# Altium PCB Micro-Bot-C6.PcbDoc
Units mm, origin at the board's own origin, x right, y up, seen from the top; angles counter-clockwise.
Board outline 64.69 x 63 mm, 2 copper layers (Top Layer, Bottom Layer); 16 components, 18 nets, 55 pads, 0 vias.
Unrouted connection lines stored in the file: 2.
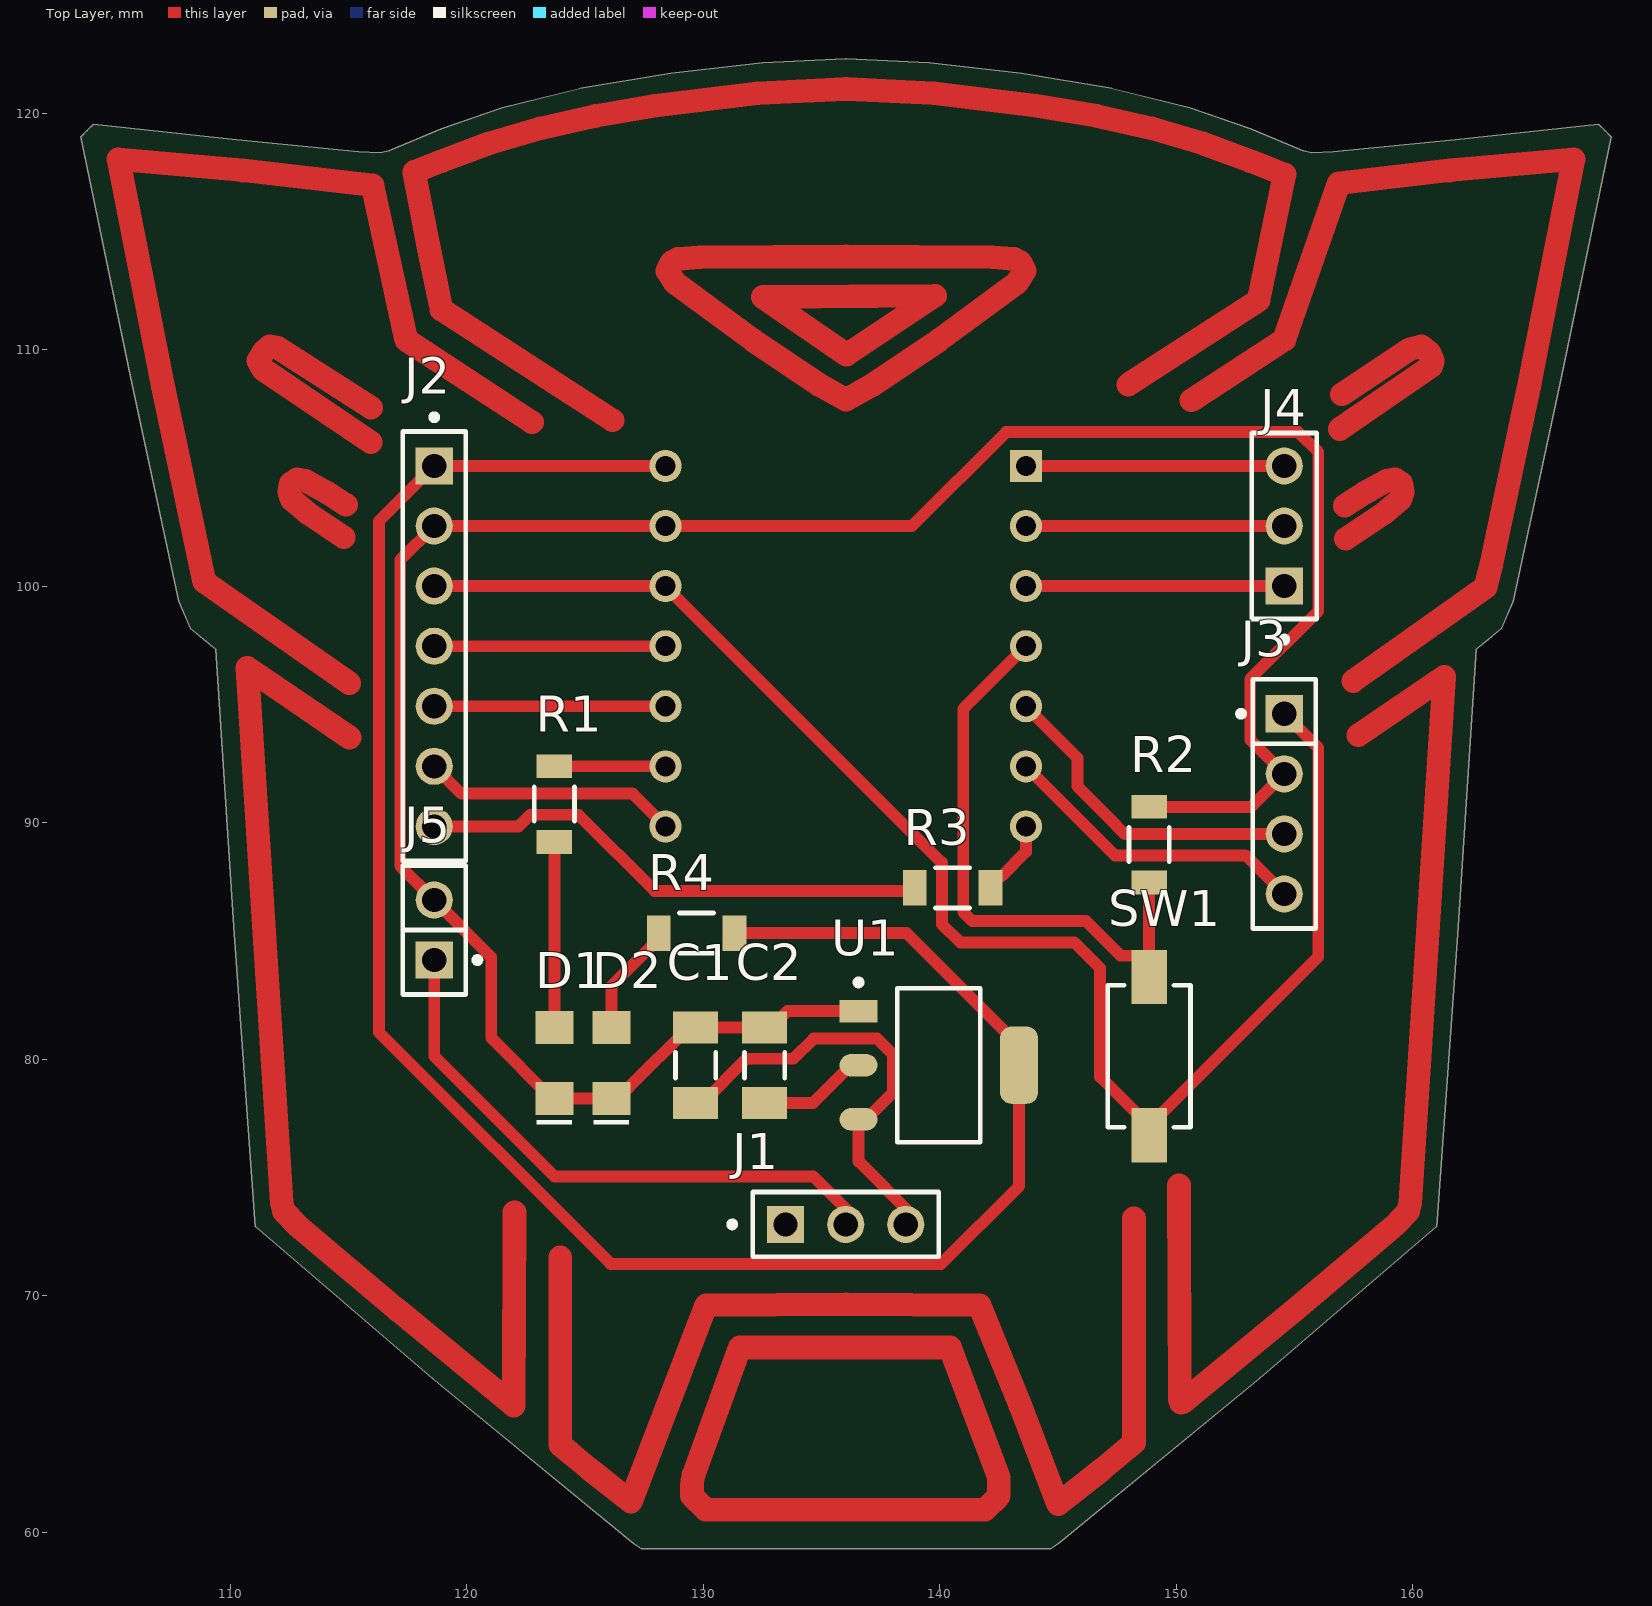
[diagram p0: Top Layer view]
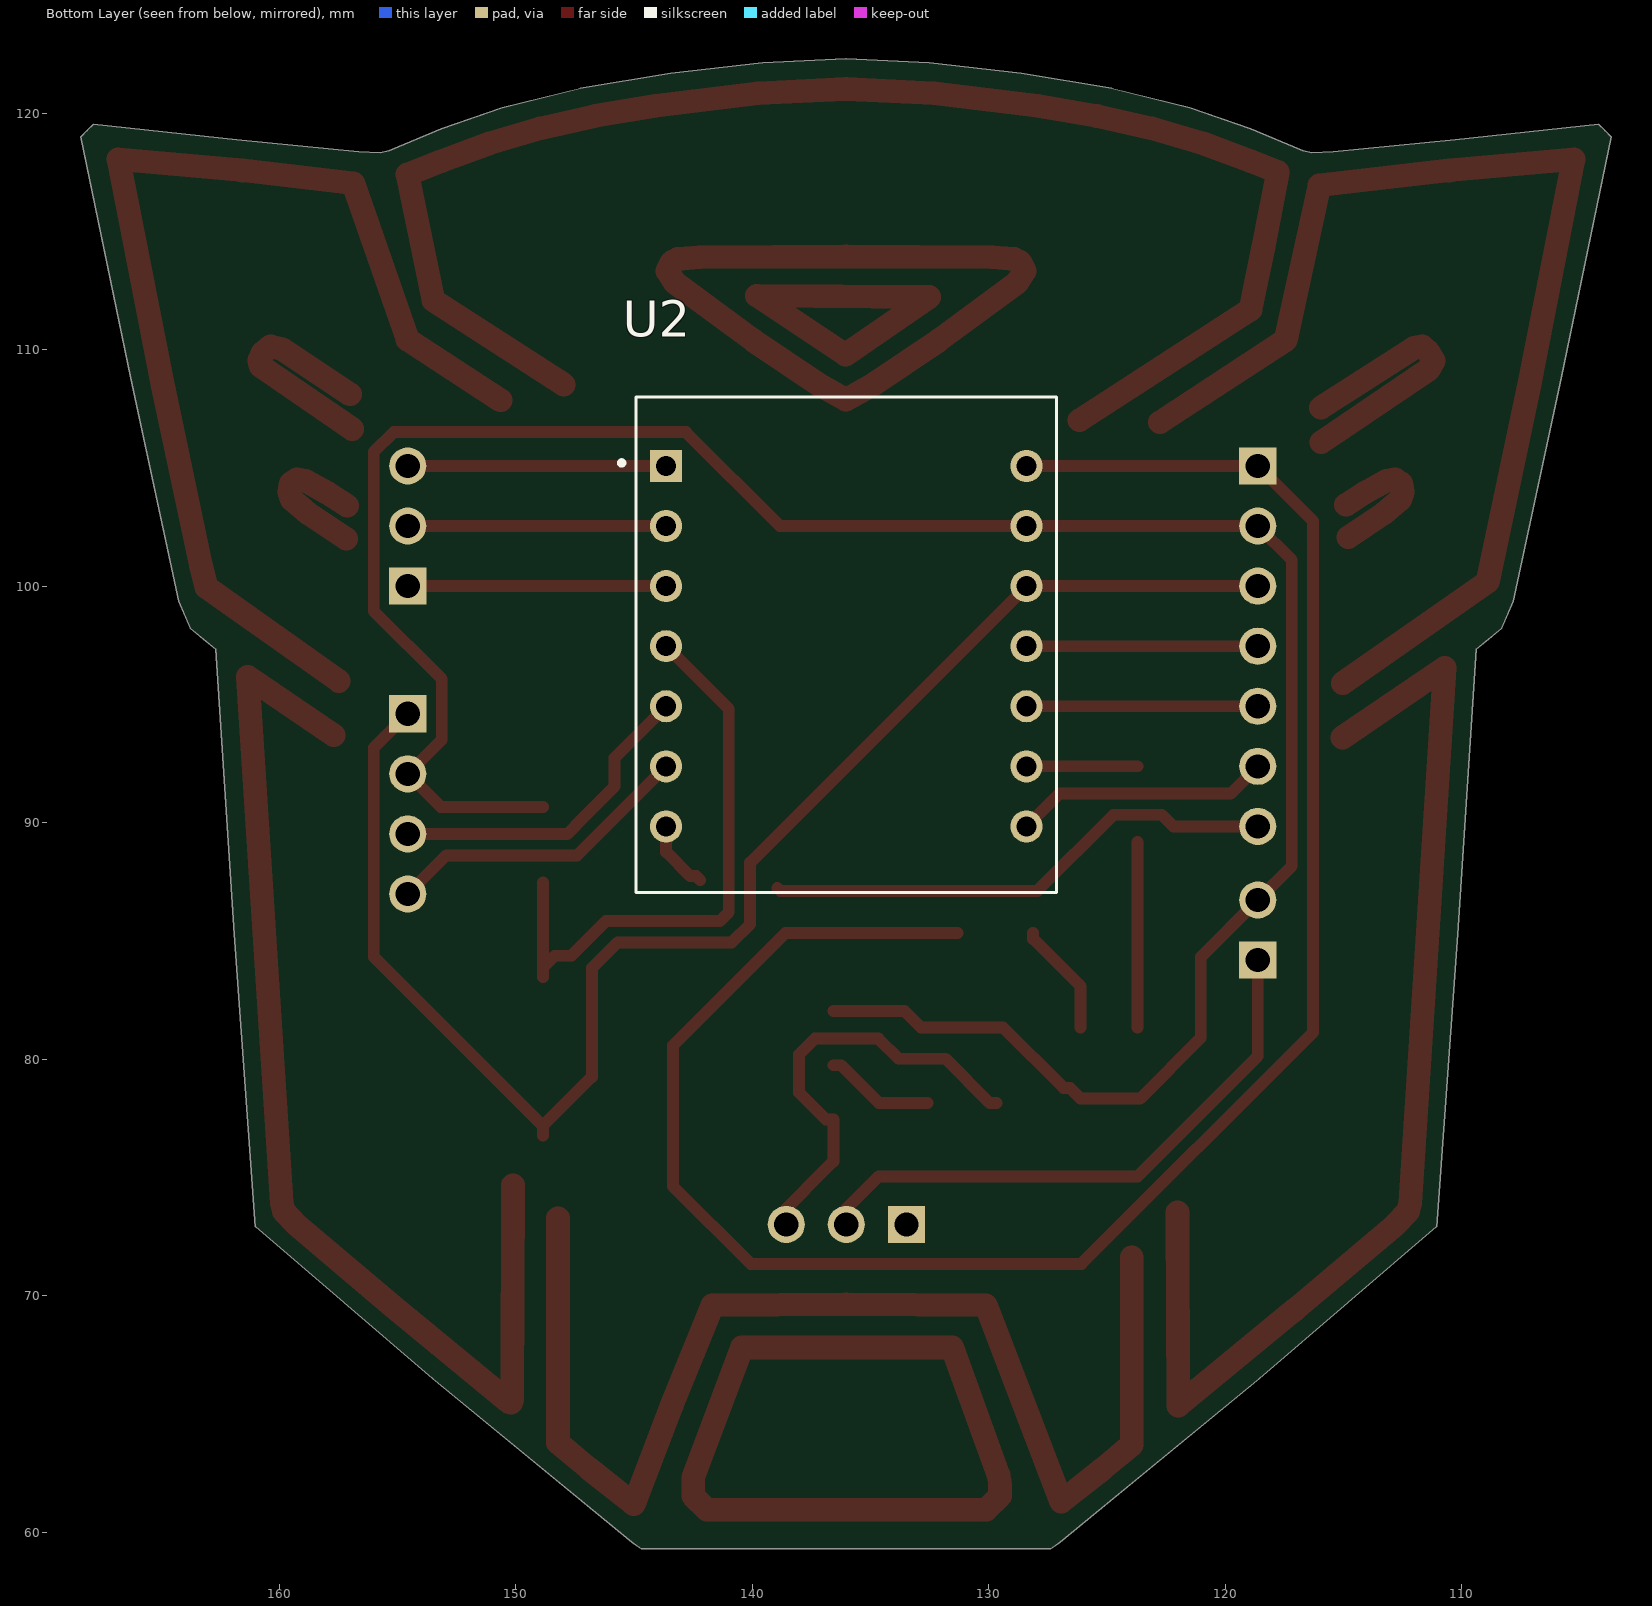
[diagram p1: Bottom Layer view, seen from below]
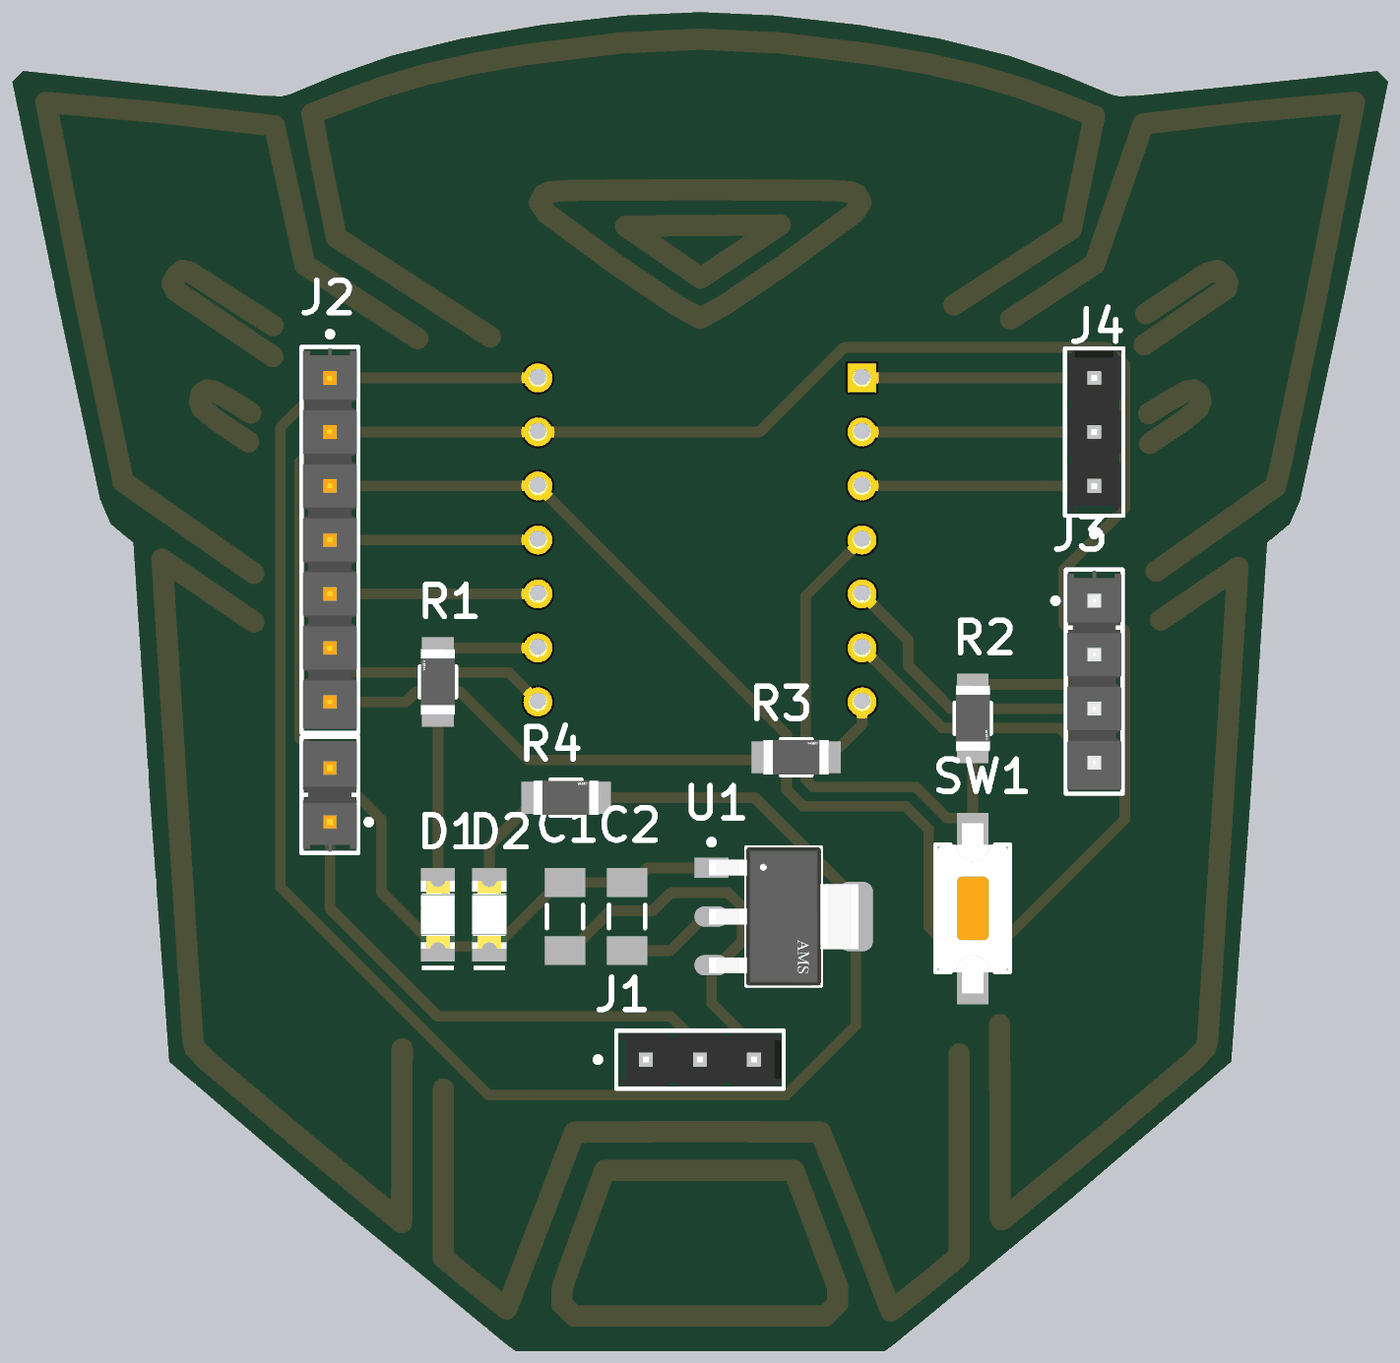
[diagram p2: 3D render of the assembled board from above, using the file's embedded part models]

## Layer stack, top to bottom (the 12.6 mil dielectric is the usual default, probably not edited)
Top Solder: solder mask 0.0102, Solder Resist, Dk 3.5
Top Layer: signal copper 0.0356
Dielectric 1: dielectric 0.32, FR-4, Dk 4.8
Bottom Layer: signal copper 0.0356
Bottom Solder: solder mask 0.0102, Solder Resist, Dk 3.5

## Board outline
108.313,98.223 108.982,97.668 109.376,97.352 110.157,85.3 111.061,72.931 118.553,66.514 126.975,59.585 127.377,59.301 144.682,59.301 145.084,59.585 153.506,66.514 160.998,72.931 161.902,85.3 162.683,97.352 163.077,97.668 163.746,98.223 164.244,99.371 166.272,108.815 168.376,119.015 168.117,119.274 167.859,119.533 161.787,118.884 156.635,118.369 155.727,118.339 155.358,118.419 153.133,119.343 150.567,120.246 147.261,121.053 143.446,121.705 139.557,122.142 136.03,122.301 132.502,122.142 128.613,121.705 124.798,121.053 121.492,120.246 118.926,119.343 116.701,118.419 116.332,118.339 115.425,118.369 110.272,118.884 104.2,119.533 103.942,119.274 103.683,119.015 105.787,108.815 107.815,99.371

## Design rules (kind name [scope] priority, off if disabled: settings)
Clearance [All] p1: gap=0.4 ignorepadtopadclearanceinfootprint=FALSE
PolygonConnect [All] p1: connectstyle=Relief reliefconductorwidth=0.254 reliefentries=4 polygonreliefangle="90 Angle" airgapwidth=0.254
RoutingVias [All] p1: holewidth=0.711 width=1.27 viastyle="Through Hole" minholewidth=0.711 minwidth=1.27 maxholewidth=0.711 maxwidth=1.27
SolderMaskExpansion [All] p1: expansion=0 istentingtop=FALSE
SupplyNets "Schematic Supply Nets_4" [InNet('VB')] p1: voltage=0.000
SupplyNets "Schematic Supply Nets_3" [InNet('+5')] p2: voltage=0.000
SupplyNets "Schematic Supply Nets_2" [InNet('GND')] p3: voltage=0.000
SupplyNets "Schematic Supply Nets_1" [InNet('+7.4')] p4: voltage=0.000
SupplyNets "Schematic Supply Nets" [InNet('+3.3')] p5: voltage=0.000
Width [All] p1: maxlimit=0.5 minlimit=0.254 preferedwidth=0.5 minimp=50.000000 maximp=50.000000 favimp=50.000000
30 further rules are at their usual default settings.

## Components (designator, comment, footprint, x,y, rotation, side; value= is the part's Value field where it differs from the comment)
C1 "10 uF" CAPC1206(3216)100_M 129.667,79.756 r270 top value=4.7pF
C2 "10 uF" CAPC1206(3216)100_M 132.588,79.756 r270 top value=4.7pF
D1 "" WL-SMCW_1206_150120xx75000 123.698,79.844 r90 top
D2 "" WL-SMCW_1206_150120xx75000 126.111,79.844 r90 top
J1 "" FP-22-28-4030-MFG 136.017,73.025 r0 top
J2 "MPU6050" FP-TSW-107-07-G-S-MFG 118.618,97.472 r270 top
J3 "I2C" FP-TSW-104-23-T-S-MFG 154.559,90.805 r270 top
J4 "" FP-22-28-4030-MFG 154.559,102.552 r90 top
J5 "BATTERY" FP-TSW-102-14-G-S-MFG 118.618,85.471 r90 top
R1 "" FP-RC1206-MFG 123.698,90.793 r90 top value=0Ω
R2 "" FP-RC1206-MFG 148.844,89.078 r270 top value=0Ω
R3 "" FP-RC1206-MFG 140.538,87.249 r0 top value=0Ω
R4 "" FP-RC1206-MFG 129.718,85.344 r0 top value=0Ω
SW1 "" 434111043826 148.844,80.137 r90 top
U1 "AMS1117" FP-AMS1117-IPC_A 139.954,79.756 r0 top
U2 "XIAO_ESP32C3" MODULE_XIAO_ESP32C3 136.017,97.536 r180 bottom

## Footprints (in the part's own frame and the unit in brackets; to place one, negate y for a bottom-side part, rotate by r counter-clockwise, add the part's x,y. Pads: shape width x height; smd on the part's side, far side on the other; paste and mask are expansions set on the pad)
434111043826 [mm] "SMD Tact Switch, body 6x3.5mm"
  rect 2.3x1.5 smd: 1(-3.35,0) 2(3.35,0)
  silkscreen extent -3,-1.75 3,1.75, body extent -4,-1.75 4,1.75, height 4.3
CAPC1206(3216)100_M [mm] "Chip Capacitor, Body 3.2x1.6mm, Height 1mm, IPC Low Density"
  rect 1.35x1.9 smd: 1(-1.6,0) 2(1.6,0)
  silkscreen extent -0.55,-0.85 0.55,0.85, body extent -1.7,-0.9 1.7,0.9, height 1
FP-22-28-4030-MFG [mm]
  rect 1.57x1.57 hole 1.02 paste-2539.97 mask+0: 1(-2.54,0)
  round 1.57 hole 1.02 paste-2539.97 mask+0: 2(0,0) 3(2.54,0)
  silkscreen extent -4.92,-1.37 3.94,1.37, body extent -4.04,-1.47 4.04,1.47, height 0.25
FP-AMS1117-IPC_A [mm]
  rect 1.604x0.952 smd paste+0 mask+0: 1(-3.395,2.29)
  rrect100% 1.604x0.952 smd paste+0 mask+0: 2(-3.395,0) 3(-3.395,-2.29)
  rrect59% 1.604x3.262 smd paste+0 mask+0: 4(3.395,0)
  silkscreen extent -3.52,-3.25 1.75,3.62, body extent -4.7,-3.75 4.7,3.75, height 0.25
FP-RC1206-MFG [mm]
  rect 1x1.5 smd paste+0 mask+0: 1(-1.6,0) 2(1.6,0)
  silkscreen extent -0.72,-0.85 0.72,0.85, body extent -2.2,-0.95 2.2,0.95, height 0.25
FP-TSW-102-14-G-S-MFG [mm]
  rect 1.57x1.57 hole 1.02 paste-2539.97 mask+0: 1(-1.27,0)
  round 1.57 hole 1.02 paste-2539.97 mask+0: 2(1.27,0)
  silkscreen extent -2.73,-1.95 2.73,1.34, body extent -2.83,-1.44 2.83,1.44, height 0.25
FP-TSW-104-23-T-S-MFG [mm]
  rect 1.57x1.57 hole 1.02 paste-2539.97 mask+0: 1(-3.81,0)
  round 1.57 hole 1.02 paste-2539.97 mask+0: 2(-1.27,0) 3(1.27,0) 4(3.81,0)
  silkscreen extent -5.27,-1.95 5.27,1.34, body extent -5.37,-1.44 5.37,1.44, height 0.25
FP-TSW-107-07-G-S-MFG [mm]
  rect 1.57x1.57 hole 1.02 paste-2539.97 mask+0: 1(-7.62,0)
  round 1.57 hole 1.02 paste-2539.97 mask+0: 2(-5.08,0) 3(-2.54,0) 4(0,0) 5(2.54,0) 6(5.08,0) 7(7.62,0)
  silkscreen extent -9.8,-1.34 9.08,1.34, body extent -9.18,-1.44 9.18,1.44, height 0.25
MODULE_XIAO_ESP32C3 [mm]
  rect 1.358x1.358 / inner round 1.358 / far side rect 1.358x1.358 hole 0.85 mask+0.102: 1(-7.62,7.557)
  round 1.358 hole 0.85 mask+0.102: 2(-7.62,5.017) 3(-7.62,2.477) 4(-7.62,-0.063) 5(-7.62,-2.603) 6(-7.62,-5.143) 7(-7.62,-7.683) 8(7.62,-7.684) 9(7.62,-5.144) 10(7.62,-2.604) 11(7.62,-0.064) 12(7.62,2.476) 13(7.62,5.016) 14(7.62,7.556)
  silkscreen extent -9.6,-10.48 8.89,10.48, body extent -8.89,-10.48 8.89,11.99, height 4.21
WL-SMCW_1206_150120xx75000 [mm] "SMD Mono-color Chip LED, body 3.2x1.6mm"
  rect 1.4x1.6 smd: 1(-1.5,0) 2(1.5,0)
  silkscreen extent -2.6,-0.75 -2.4,0.75, body extent -1.6,-0.8 1.6,0.8, height 0.68

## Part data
C1 C2: library part CMP-1037-00368-1, "CAP 4.7pF 10V ±0.25pF 1206 (3216 Metric) Thickness 1mm SMD", Case-EIA=1206, Case-Metric=3216, Rated Voltage="10 V", Tolerance=Â±0.25pF
D1 D2: library part CMP-1426-00015-3, "WL-SMCW SMT Mono-Color Chip LED Waterclear", Case Code (Imperial)=1206, Case Code (Metric)=3216, Color=Blue, Forward Current=100mA, Forward Voltage=3.2V, Manufacturer Package Identifier=LED_1206, Max Operating Temperature=85°C, Max Reverse Voltage (DC)=5V, Min Operating Temperature=-40°C, Test Current=20mA
J1 J4: library part CMP-04776-000098-1, "CONN HEADER VERT 3POS 2.54MM", Current Rating=4A, Manufacturer=Molex, Manufacturer Part Number=22-28-4030, Temperature="-40°C to +80°C", Temperature Range High=+80°C, Temperature Range Low=-40°C, Voltage Rating=500V
J2: library part CMP-02766-000065-1, "CONN HEADER VERT 7POS 2.54MM", Manufacturer=SAMTEC, Manufacturer Part Number=TSW-107-07-G-S, Package=0, Temperature="-55°C to +125°C", Temperature Range High=+125°C, Temperature Range Low=-55°C
J3: library part CMP-02766-001388-1, "CONN HEADER VERT 4POS 2.54MM", Color=Black, Max Current Rating=7.6A, Max Operating Temperature=105°C, Max Voltage Rating (AC)=550V, Min Operating Temperature=-55°C, Package Quantity=1
J5: library part CMP-02766-001740-1, "CONN HEADER VERT 2POS 2.54MM", Color=Black, Flammability Rating="UL94 V-0", Max Current Rating=7.6A, Max Operating Temperature=125°C, Max Voltage Rating (AC)=550V, Min Operating Temperature=-55°C, Package Quantity=1
R1 R2 R3 R4: library part CMP-2100-03681-2, "RES SMD 0 OHM JUMPER 1/4W 1206", Manufacturer=YAGEO, Manufacturer Part Number=RC1206JR-070RL, Package=RC1206, Power Rating=0.25W, Resistance=0Ω, Temperature="-55°C to +155°C", Temperature Coefficient=300ppm/°C, Temperature Range High=+155°C, Temperature Range Low=-55°C, Tolerance=5%, Voltage Rating=200V
SW1: library part CMP-1459-00002-3, "Rectangular Button WS-TASV White Surface Mount Tactile Switch 4.30mm 50mA 0.05A @ 12VDC 260gf", Color=White, Contact Current Rating=50mA, Contact Resistance=100mΩ, Insulation Resistance=100MΩ, Max Operating Temperature=85°C, Min Operating Temperature=-40°C, Operating Force=260N, Voltage Rating=12V
U1: library part CMP-209535-000001-1, "LDO Voltage Regulators 1A, 3.3V", Dropout Voltage=1.1V, Manufacturer="Advanced Monolithic Systems", Manufacturer Part Number=AMS1117-3.3, Max Junction Temp=+125°C, Max Power Dissipation=1.2W, Max Supply Voltage=15V, Nominal Supply Current=5mA, Output Current=1A, Output Voltage=3.3V, Temperature="-40°C to +125°C", Temperature Range Low=-40°C
U2: "Dev.kit: evaluation; u.FL antenna,prototype board; XIAO; PIN: 2x7", Package=None

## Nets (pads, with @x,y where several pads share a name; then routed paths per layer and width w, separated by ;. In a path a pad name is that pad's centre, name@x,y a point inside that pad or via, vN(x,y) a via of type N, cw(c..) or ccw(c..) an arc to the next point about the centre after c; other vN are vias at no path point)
+3.3: J2.3 J3.1 SW1.1 U2.12 | length 65.3
  Top Layer w0.5: J2.3 U2.12 140.088,88.321 140.088,85.718 140.857,84.949 145.683,84.949 146.772,83.86 146.772,79.259 SW1.1@148.844,77.187 ; SW1.1 SW1.1@148.844,77.187 ; J3.1 155.994,93.18 155.994,84.337 SW1.1@148.844,77.187
+5: C2.2 J2.1 R4.2 U1.2 U1.4 U2.14 | length 91.8
  Top Layer w0.5: U2.14 J2.1 116.283,102.758 116.283,81.147 126.077,71.353 140.06,71.353 143.349,74.642 U1.4 143.349,80.585 138.59,85.344 R4.2 ; C2.2 134.633,78.156 136.233,79.756 U1.2
+7.4: C1.2 J1.3 U1.3 | length 18.4
  Top Layer w0.5: C1.2 129.942,78.156 131.817,80.031 133.807,80.031 134.658,80.882 137.352,80.882 138.011,80.222 138.011,78.592 136.885,77.466 U1.3 136.559,75.686 J1.3@138.888,73.356
A0: J4.3 U2.1 | length 10.9
  Top Layer w0.5: U2.1 J4.3
A1: J4.2 U2.2 | length 10.9
  Top Layer w0.5: U2.2 J4.2
A2: J4.1 U2.3 | length 10.9
  Top Layer w0.5: U2.3 J4.1
BUTTON: R2.2 SW1.2 U2.4 | length 25.6
  Top Layer w0.5: U2.4 140.988,94.823 140.988,86.23 141.369,85.849 146.18,85.849 147.642,84.387 148.344,84.387 148.844,83.887 SW1.2 R2.2
D8: R1.2 U2.9 | length 4.7
  Top Layer w0.5: R1.2 U2.9
D9: J2.5 U2.10 | length 9.8
  Top Layer w0.5: J2.5 U2.10
D10: J2.4 U2.11 | length 9.8
  Top Layer w0.5: J2.4 U2.11
GND: C1.1 C2.1 D1.1 D2.1 J2.2 J3.2 J5.2 R2.1 U1.1 U2.13 | length 103
  Top Layer w0.5: U1.1 133.553,82.046 132.863,81.356 C2.1 C1.1 129.392,81.356 126.83,78.794 126.561,78.794 D2.1 123.598,78.344 121.031,80.911 121.031,84.328 J5.2 117.183,88.176 117.183,101.118 J2.2 U2.13 138.82,102.552 142.795,106.527 155.153,106.527 155.994,105.687 155.994,98.958 153.124,96.088 153.124,93.51 J3.2 153.162,90.678 R2.1
NetD1_2: D1.2 R1.1 | length 7.8
  Top Layer w0.5: D1.2 R1.1
NetD2_2: D2.2 R4.1 | length 4.8
  Top Layer w0.5: D2.2 126.111,83.087 128.118,85.094 R4.1
RX: J2.6 U2.8 | length 10.8
  Top Layer w0.5: J2.6 119.768,91.243 127.007,91.243 U2.8
SCL: J3.4 U2.6 | length 13.2
  Top Layer w0.5: U2.6 147.401,88.628 152.926,88.628 J3.4
SDA: J3.3 U2.5 | length 13.9
  Top Layer w0.5: U2.5 145.813,92.757 145.813,91.55 147.444,89.919 147.444,89.909 147.825,89.528 154.552,89.528 J3.3
TX: J2.7 R3.1 R3.2 U2.7 | length 24.9
  Top Layer w0.5: J2.7 122.189,89.852 122.679,90.343 124.717,90.343 127.938,87.122 138.811,87.122 R3.1 ; R3.2@142.189,87.575 142.363,87.749 142.613,87.749 143.637,88.773 U2.7
VB: J1.2 J5.1 | length 24.6
  Top Layer w0.5: J5.1 118.618,80.137 123.698,75.057 134.648,75.057 J1.2@136.348,73.356
pads on no net: J1.1
copper on no net: | length 433.6
  Top Layer w1: 114.791,102.083 113.282,103.093 112.595,103.673 112.492,103.987 112.556,104.352 112.818,104.529 113.177,104.469 114.103,103.959 114.891,103.448 ; 115.033,95.903 108.899,100.201 107.121,108.615 105.265,118.059 110.52,117.588 116.009,116.951 117.437,110.418 122.75,106.94 ; 115.038,93.614 110.717,96.563 111.43,85.363 112.173,73.92 112.264,73.583 112.822,72.984 117.065,69.409 121.987,65.359 122.012,73.533 ; 115.942,106.098 111.388,109.174 111.183,109.536 111.408,109.928 111.67,110.151 112.008,110.088 115.943,107.556 ; 123.952,71.636 123.952,63.703 125.203,62.664 126.928,61.297 130.117,69.606 136.03,69.65 141.682,69.608 143.383,65.405 144.999,61.193 146.856,62.664 148.209,63.788 148.209,73.29 ; 126.159,107.025 118.924,111.702 118.364,114.427 117.769,117.524 118.928,117.983 120.955,118.735 123.104,119.367 125.421,119.892 127.953,120.322 132.304,120.853 136.032,121.031 139.749,120.857 144.067,120.329 146.623,119.895 148.95,119.369 151.101,118.736 153.131,117.983 154.567,117.414 153.475,112.095 147.962,108.532 ; 150.107,74.676 150.139,65.626 150.194,65.492 150.267,65.51 155.189,69.566 159.261,73.004 159.798,73.585 159.886,73.92 160.629,85.363 161.318,96.182 157.681,93.7 ; 150.628,107.864 154.567,110.442 156.863,117.045 156.866,117.046 161.539,117.588 166.794,118.059 164.938,108.615 163.303,100.875 163.072,99.969 157.472,96.001 ; 156.903,106.654 160.78,109.304 160.837,109.562 160.709,109.855 160.354,110.145 159.876,110.032 156.987,108.12 ; 157.121,103.414 157.954,103.954 158.883,104.466 159.243,104.528 159.503,104.352 159.567,103.987 159.464,103.673 158.778,103.093 157.163,102.012 ; 128.469,113.338 128.801,112.839 132.117,110.4 134.874,108.536 136.03,107.894 137.186,108.536 139.942,110.4 143.258,112.839 143.59,113.338 143.403,113.707 143.131,113.843 142.222,113.915 136.03,113.949 129.837,113.915 128.928,113.843 128.656,113.707 128.469,113.338 ; 129.52,61.546 130.106,60.96 141.559,60.96 141.909,60.96 142.495,61.546 142.495,62.311 140.433,67.818 131.533,67.818 129.58,62.426 129.535,62.171 129.52,61.999 129.52,61.546 ; 132.523,112.235 136.052,109.792 139.79,112.293 132.523,112.235

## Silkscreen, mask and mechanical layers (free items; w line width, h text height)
Mechanical 1:
  lines w1: 103.683,119.015 103.942,119.274 104.2,119.533 110.272,118.884 115.425,118.369 116.332,118.339 116.701,118.419 118.926,119.343 121.492,120.246 124.798,121.053 128.613,121.705 132.502,122.142 136.03,122.301 139.557,122.142 143.446,121.705 147.261,121.053 150.567,120.246 153.133,119.343 155.358,118.419 155.727,118.339 156.635,118.369 161.787,118.884 167.859,119.533 168.117,119.274 168.376,119.015 166.272,108.815 164.244,99.371 163.746,98.223 163.077,97.668 162.683,97.352 161.902,85.3 160.998,72.931 153.506,66.514 145.084,59.585 144.682,59.301 136.03,59.301 127.377,59.301 126.975,59.585 118.553,66.514 111.061,72.931 110.157,85.3 109.376,97.352 108.982,97.668 108.313,98.223 107.815,99.371 105.787,108.815 103.683,119.015 ; 155.189,69.566 155.189,69.566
